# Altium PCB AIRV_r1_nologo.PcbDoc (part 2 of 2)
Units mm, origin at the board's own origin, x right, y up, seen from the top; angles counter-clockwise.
Board outline 65 x 30 mm, 4 copper layers (Top Layer, GND, MidLayer1, Bottom Layer), stack 0.732 mm thick; 130 components, 121 nets, 598 pads, 392 vias.
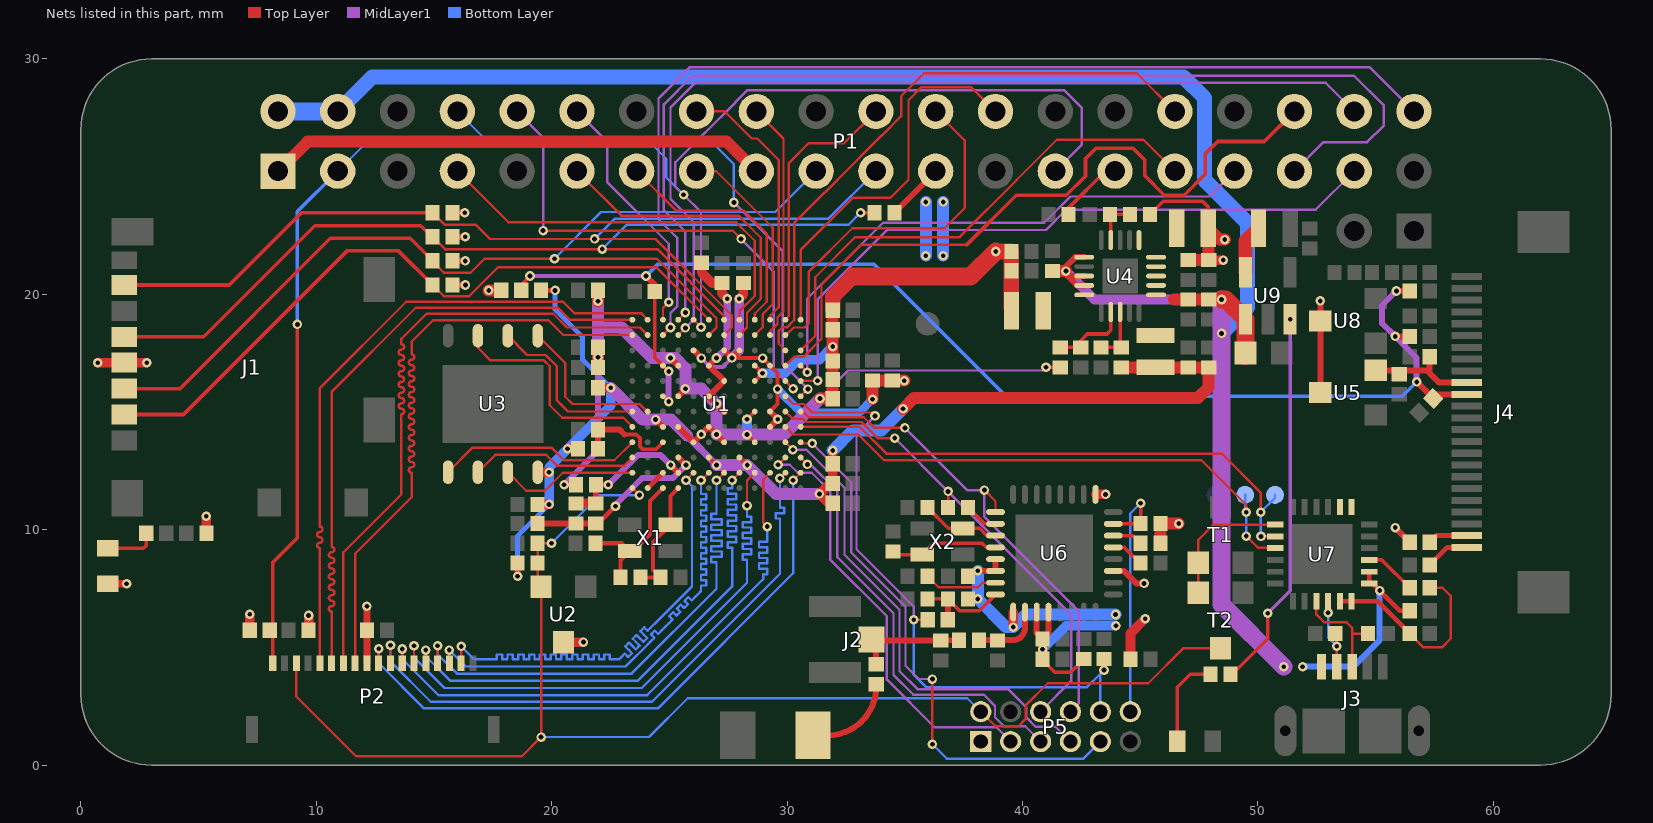
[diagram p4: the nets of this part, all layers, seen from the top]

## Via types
v1: diameter 0.406, hole 0.203, Top Layer to Bottom Layer, tented both sides, 392 vias

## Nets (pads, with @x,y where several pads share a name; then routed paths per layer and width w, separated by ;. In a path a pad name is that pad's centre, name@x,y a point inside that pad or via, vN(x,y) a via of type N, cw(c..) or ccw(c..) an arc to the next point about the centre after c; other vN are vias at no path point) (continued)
I2C_SDA: P1.3 P1.27 P2.1 R17.1 U1.A5 | length 68.6
  Top Layer w0.102: U1.A5@26.024,18.919 v1(26.34,18.604) ; U1.A5@26.027,18.922 U1.A5@26.027,18.952
  Top Layer w0.152: R17.1@8.02,5.731 R17.1@8.15,5.601 ; P2.1@8.15,4.333 R17.1@8.15,5.601 ; v1(9.195,18.72) 9.195,9.652 8.15,8.607 R17.1@8.15,5.601
  MidLayer1 w0.102: v1(26.34,18.604) 26.34,23.495 v1(25.603,24.232) 25.248,24.587 25.248,25.604 26.511,26.868 26.524,26.868 27.788,28.131 27.788,28.144 28.316,28.672 28.329,28.672 28.333,28.677 41.76,28.677 42.52,27.917 42.52,26.36 P1.27@41.39,25.23
  Bottom Layer w0.102: P1.3@10.91,25.23 11.969,26.289 24.333,26.289 24.867,25.756 24.867,24.968 v1(25.603,24.232)
  Bottom Layer w0.152: v1(9.195,18.72) 9.195,23.515 P1.3@10.91,25.23
I2S_BCK: P1.12 U1.A3 | length 10.6
  Top Layer w0.102: U1.A3@24.724,18.919 24.724,19.416 v1(24.968,19.66)
  MidLayer1 w0.102: P1.12@21.07,27.77 22.352,26.488 22.352,24.765 24.968,22.149 v1(24.968,19.66)
I2S_DI: P1.38 U1.B4 | length 40.3
  Top Layer w0.102: U1.B4@25.377,18.272 v1(25.679,18.575)
  MidLayer1 w0.102: v1(25.679,18.575) 26.035,18.93 26.035,23.063 25.044,24.054 25.044,27.941 26.085,28.981 52.879,28.981 P1.38@54.09,27.77
I2S_DO: P1.40 U1.B3 | length 44
  Top Layer w0.102: U1.B3@24.727,18.272 v1(25.044,18.59)
  MidLayer1 w0.102: v1(25.044,18.59) 25.044,19.202 25.324,19.482 25.324,22.403 24.536,23.19 24.536,28.321 25.857,29.642 54.758,29.642 P1.40@56.63,27.77
I2S_WS: P1.35 U1.A4 | length 46.7
  Top Layer w0.102: U1.A4@25.374,18.919 v1@25.679,19.225
  MidLayer1 w0.102: v1(25.679,19.228) 25.679,22.657 24.765,23.571 24.765,28.067 25.984,29.286 54.077,29.286 55.347,28.016 55.347,27.178 54.635,26.467 52.787,26.467 P1.35@51.55,25.23
IO11: P1.37 U1.E12 | length 29.2
  Top Layer w0.102: U1.E12@30.574,16.319 30.574,16.332 v1(31.293,16.332)
  MidLayer1 w0.102: v1(31.293,16.332) 31.293,19.787 34.239,22.733 40.996,22.733 41.859,23.597 52.457,23.597 P1.37@54.09,25.23
IO_12: P1.36 U1.D11 | length 30.4
  Top Layer w0.102: U1.D11@29.924,16.969 30.297,17.342 30.689,17.342 31.461,18.114 31.461,20.422 33.138,22.098 37.617,22.098
  Top Layer w0.152: 37.617,22.098 39.726,24.206 41.859,24.206 42.672,25.019 42.672,25.756 43.129,26.213 44.679,26.213 45.187,25.705 45.187,25.044 46.017,24.214 46.871,24.214 47.752,25.095 47.752,25.959 48.285,26.492 50.272,26.492 P1.36@51.55,27.77
IO_13: P1.33 U1.D12 | length 24
  Top Layer w0.102: U1.D12@30.574,16.969 v1(30.856,16.688) v1@30.856,16.716
  MidLayer1 w0.102: v1(30.856,16.688) 30.856,19.816 34.077,23.038 40.609,23.038 40.919,23.038 42.037,24.155 47.935,24.155 P1.33@49.01,25.23
IO_14: P1.32 U1.C11 | length 25.9
  Top Layer w0.102: U1.C11@29.924,17.619 29.642,17.902 29.642,18.448 29.79,18.597 29.994,18.597 30.297,18.9 30.297,23.033 31.591,24.328 31.604,24.328 32.132,24.856 32.132,24.869 34.01,26.746 34.022,26.746 34.849,27.573 34.849,28.423 35.814,29.388 44.852,29.388 P1.32@46.47,27.77
IO_15: P1.31 U1.C12 | length 21.6
  Top Layer w0.102: U1.C12@30.574,17.619 31.191,18.236 31.191,20.726 32.893,22.428 37.324,22.428 39.752,24.856 39.752,24.869 41.452,26.568 45.132,26.568 P1.31@46.47,25.23
IO_17: P1.26 U1.A12 | length 16.5
  Top Layer w0.102: U1.A12@30.574,18.919 30.574,21.887 32.791,24.105 34.392,24.105 35.154,24.867 35.154,28.245 35.712,28.804 37.816,28.804 P1.26@38.85,27.77
IO_18: P1.24 U1.B11 | length 15.7
  Top Layer w0.102: U1.B11@29.924,18.269 29.954,18.269 30.277,18.593 30.734,18.593 30.912,18.771 30.912,20.955 32.766,22.809 36.678,22.809 37.541,23.673 37.541,26.539 P1.24@36.31,27.77
IO_19: P1.22 U1.A11 | length 11.3
  Top Layer w0.102: U1.A11@29.924,18.919 30.074,19.069 30.074,25.578 30.912,26.416 32.416,26.416 P1.22@33.77,27.77
IO_20: P1.18 U1.B10 | length 10.2
  Top Layer w0.102: P1.18@28.69,27.77 29.845,26.615 29.845,19.279 29.591,19.025 29.591,18.745 29.274,18.428 U1.B10@29.274,18.269
IO_21: P1.16 U1.A10 | length 11.3
  Top Layer w0.102: P1.16@26.15,27.77 27.348,27.77 28.499,26.619 28.727,26.619 29.642,25.705 29.642,19.456 29.274,19.089 U1.A10@29.274,18.919
IO_22: P1.15 U1.B9 | length 9.1
  Top Layer w0.102: P1.15@26.15,25.23 26.987,25.23 29.388,22.829 29.388,19.583 28.956,19.152 28.956,18.601 U1.B9@28.624,18.269
IO_23: P1.13 U1.A9 | length 10.5
  Top Layer w0.102: P1.13@23.61,25.23 25.294,23.546 28.169,23.546 29.134,22.581 29.134,19.685 28.624,19.175 U1.A9@28.624,18.919
IO_24: P1.11 U1.B8 | length 13.5
  Top Layer w0.102: P1.11@21.07,25.23 22.957,23.343 27.94,23.343 28.88,22.403 28.88,19.804 28.296,19.22 28.296,18.591 U1.B8@27.974,18.269
IO_25: P1.7 U1.A8 | length 17.5
  Top Layer w0.102: P1.7@15.99,25.23 18.157,23.063 27.833,23.063 28.621,22.276 28.621,19.934 27.974,19.287 U1.A8@27.974,18.919
ISP_RX: TP3.1 U1.H11 U7.21 | length 24.5
  Top Layer w0.102: U1.H11@29.927,14.372 30.253,14.046 33.02,14.046 34.112,12.954 47.6,12.954 49.505,11.049 v1(49.505,10.744) ; v1(49.505,9.728) 50.001,9.231 50.73,9.231 U7.21@50.73,9.216
  Bottom Layer w0.102: TP3.1@49.454,11.481 49.454,10.795 v1(49.505,10.744) v1(49.505,9.728)
ISP_TX: TP5.1 U1.H12 U7.20 | length 24.1
  Top Layer w0.102: U1.H12@30.577,14.372 33.075,14.372 34.214,13.233 48.463,13.233 50.114,11.582 v1(50.114,10.744) ; v1(50.128,9.716) U7.20@50.73,9.716
  Bottom Layer w0.102: v1@50.114,9.73 v1(50.114,10.744) 50.724,11.354 TP5.1@50.724,11.481
LCD_CS: P2.5 U1.A2 | length 28
  Top Layer w0.102: P2.5@10.15,4.333 10.15,9.144 10.15,9.22 cw(c10.15,9.335) 10.15,9.449 ccw(c10.15,9.563) 10.15,9.677 cw(c10.15,9.792) 10.15,9.906 ccw(c10.15,10.02) 10.15,10.135 10.15,16.017 13.818,19.685 20.472,19.685 20.955,19.202 23.791,19.202 U1.A2@24.074,18.919
LCD_DC: P2.7 U1.B2 | length 27.8
  Top Layer w0.102: P2.7@11.15,4.333 11.15,9.042 13.614,11.506 13.614,14.808 13.614,14.91 ccw(c13.614,15.024) 13.614,15.138 cw(c13.617,15.253) 13.614,15.367 ccw(c13.614,15.481) 13.614,15.596 cw(c13.614,15.71) 13.614,15.824 ccw(c13.614,15.938) 13.614,16.053 cw(c13.614,16.167) 13.614,16.281 ccw(c13.614,16.396) 13.614,16.51 cw(c13.614,16.624) 13.614,16.739 ccw(c13.614,16.853) 13.614,16.967 cw(c13.614,17.081) 13.614,17.196 ccw(c13.614,17.31) 13.614,17.424 cw(c13.614,17.539) 13.614,17.653 ccw(c13.614,17.767) 13.614,17.882 13.614,18.11 14.681,19.177 20.066,19.177 20.65,18.593 23.751,18.593 U1.B2@24.074,18.269 ; U1.B2@24.077,18.272 U1.B2@24.091,18.272
LCD_RST: P2.6 U1.A1 | length 27.6
  Top Layer w0.102: P2.6@10.65,4.333 10.65,6.426 10.65,6.528 cw(c10.65,6.642) 10.65,6.756 ccw(c10.65,6.871) 10.65,6.985 cw(c10.65,7.099) 10.65,7.214 ccw(c10.65,7.328) 10.65,7.442 cw(c10.65,7.556) 10.65,7.671 ccw(c10.65,7.785) 10.65,7.899 cw(c10.65,8.014) 10.65,8.128 ccw(c10.65,8.242) 10.65,8.357 cw(c10.65,8.471) 10.65,8.585 ccw(c10.65,8.7) 10.65,8.814 cw(c10.65,8.928) 10.65,9.042 ccw(c10.65,9.157) 10.65,9.271 10.65,12.268 10.65,15.672 10.65,15.857 14.224,19.431 20.269,19.431 20.777,18.923 U1.A1@23.426,18.923
LCD_WR: P2.8 U1.B1 | length 27.5
  Top Layer w0.102: P2.8@11.65,4.333 11.65,8.983 14.046,11.379 14.046,12.268 14.046,12.421 cw(c14.046,12.535) 14.046,12.649 ccw(c14.046,12.763) 14.046,12.878 cw(c14.046,12.992) 14.046,13.106 ccw(c14.046,13.221) 14.046,13.335 cw(c14.046,13.449) 14.046,13.564 ccw(c14.046,13.678) 14.046,13.792 cw(c14.046,13.906) 14.046,14.021 ccw(c14.046,14.135) 14.046,14.249 cw(c14.046,14.364) 14.046,14.478 ccw(c14.046,14.592) 14.046,14.707 cw(c14.046,14.821) 14.046,14.935 ccw(c14.046,15.05) 14.046,15.164 cw(c14.046,15.278) 14.046,15.392 ccw(c14.046,15.507) 14.046,15.621 cw(c14.046,15.735) 14.046,15.85 ccw(c14.046,15.964) 14.046,16.078 cw(c14.046,16.192) 14.046,16.307 ccw(c14.046,16.421) 14.046,16.535 cw(c14.046,16.65) 14.046,16.764 ccw(c14.046,16.878) 14.046,16.993 cw(c14.046,17.107) 14.046,17.221 ccw(c14.046,17.335) 14.046,17.45 14.046,17.983 14.961,18.898 19.863,18.898 20.488,18.272 U1.B1@23.427,18.272
NetA1_1: A1.1 R42.1 | length 4
  Top Layer w0.254: A1.1@31.1,1.285 A1.1@31.1,1.27 31.724,1.27 ccw(c31.724,3.328) 33.782,3.328 R42.1@33.782,3.436
NetC5_2: C5.2 R1.2 U1.J3 | length 4.3
  Top Layer w0.152: 23.089,14.046 23.597,14.046 23.749,13.894 23.749,13.538 23.876,13.411 24.416,13.411 U1.J3@24.724,13.719 U1.J3@24.727,13.722
  Top Layer w0.254: R1.2@21.964,13.437 C5.2@21.964,14.249 22.885,14.249 23.089,14.046
NetC6_1: C6.1 C7.1 R4.2 U1.K4 | length 7.8
  Top Layer w0.203: C7.1@21.869,10.268 21.978,10.268 v1(22.708,10.998)
  Top Layer w0.254: R4.2@19.399,10.262 19.406,10.268 C6.1@21.031,10.268 C7.1@21.869,10.268 ; U1.K4@25.377,13.072 v1(25.702,12.747)
  MidLayer1 w0.254: v1(22.708,10.998) 22.708,11.065 23.835,12.192 25.148,12.192 v1(25.702,12.747)
NetC6_2: C6.2 C7.2 R2.1 U1.L4 | length 6
  Top Layer w0.254: C7.2@21.869,11.118 21.888,11.137 R2.1@21.888,11.913 v1(22.403,11.913) ; v1(25.052,12.747) U1.L4@25.377,12.422
  Top Layer w0.406: C6.2@21.031,11.118 C7.2@21.869,11.118
  MidLayer1 w0.254: v1(22.403,11.913) 23.675,13.184 24.615,13.184 v1(25.052,12.747)
NetC8_2: C8.2 R5.1 U1.M3 X1.1 | length 6.2
  Top Layer w0.178: C8.2@21.863,9.423 22.987,9.423 X1.1@23.317,9.093 ; R5.1@22.918,7.976 22.918,8.694 X1.1@23.317,9.093 ; U1.M3@24.727,11.772 U1.M3@24.724,11.769 24.181,11.226 24.181,9.804 23.47,9.093 X1.1@23.317,9.093
NetC9_1: C9.1 R5.2 U1.M4 X1.3 | length 5.2
  Top Layer w0.178: R5.2@23.768,7.976 C9.1@24.619,7.976 24.308,8.287 24.308,9.474 X1.3@25.044,10.211 25.044,11.44 U1.M4@25.374,11.769 U1.M4@25.377,11.772
NetC35_2: C35.2 R30.2 U7.5 U7.6 | length 8.5
  Top Layer w0.102: C35.2@56.446,5.588 57.03,5.004 57.81,5.004 58.191,5.385 58.191,7.188 57.849,7.531 R30.2@57.296,7.531
  Top Layer w0.203: U7.5@53.48,6.966 U7.6@53.98,6.966 55.086,6.966 56.446,5.607 C35.2@56.446,5.588
NetC41_2: C41.2 J2.1 L4.2 R42.2 | length 4.8
  Top Layer w0.254: J2.1@33.579,5.334 J2.1@33.612,5.302 ; R42.2@33.782,4.286 33.782,5.131 J2.1@33.612,5.302 ; L4.2@37.294,5.309 C41.2@36.525,5.302 J2.1@33.612,5.302
NetC50_2: C50.2 U6.28 X2.1 | length 4.7
  Top Layer w0.152: C50.2@34.493,9.075 34.627,8.941 X2.1@35.738,8.941 36.216,9.419 38.283,9.419 38.451,9.25 U6.28@38.851,9.25
NetC51_1: C51.1 U6.27 X2.3 | length 3.4
  Top Layer w0.152: C51.1@35.96,10.947 36.849,10.058 X2.3@37.465,10.058 38.176,10.058 38.485,9.75 U6.27@38.851,9.75
NetD1_2: D1.2 J3.3 U7.3 | length 4.6
  Top Layer w0.102: U7.3@52.48,6.966 52.48,6.397 52.807,6.071 53.772,6.071 53.772,6.065 54,5.837 J3.3@54,4.18 ; 54,5.588 D1.2@54.668,5.588
NetD2_2: D2.2 J3.2 U7.4 | length 3.5
  Top Layer w0.102: v1(52.98,6.473) U7.4@52.98,6.966 ; D2.2@53.282,5.588 53.35,5.52 v1(53.35,5.055) J3.2@53.35,4.18
  Bottom Layer w0.102: v1(52.98,6.473) 52.98,5.425 v1(53.35,5.055)
NetDS1_K: DS1.K R49.2 | length 2.2
  Top Layer w0.152: DS1.K@1.143,9.208 2.655,9.208 2.775,9.329 R49.2@2.775,9.855
NetDS3_A: DS3.A R43.2 | length 3.9
  Top Layer w0.152: DS3.A@46.57,1.016 46.57,3.314 47.117,3.861 R43.2@47.987,3.861
NetJ4_23: J4.23 R38.1 | length 1.7
  Top Layer w0.203: R38.1@57.296,9.474 57.571,9.75 J4.23@58.875,9.75
NetJ4_24: J4.24 R33.1 | length 1.9
  Top Layer w0.203: R33.1@57.296,8.503 58.043,9.25 J4.24@58.875,9.25
NetL1_1: L1.1 U4.11
NetL2_1: L2.1 U4.20
NetL3_1: L3.1 U4.6
NetL5_2: L5.2 U9.5 | length 2.1
  Top Layer w0.61: U9.5@49.469,20.939 49.469,22.255 L5.2@50.023,22.809
NetP1_23: P1.23 R23.2 | length 2.5
  Top Layer w0.254: R23.2@34.563,23.47 36.31,25.217 P1.23@36.31,25.23
NetP1_29: P1.29 R21.1 | length 2.9
  Top Layer w0.152: R21.1@41.954,23.393 41.954,23.666 43.518,25.23 P1.29@43.93,25.23
NetR8_2: R8.2 R9.1 U4.3 | length 2.4
  Top Layer w0.152: R9.1@43.332,17.748 R8.2@44.196,17.748 44.145,17.799 U4.3@44.145,19.252
NetR10_2: R10.2 R11.1 U4.14 | length 2
  Top Layer w0.152: U4.14@43.745,22.302 43.745,23.355 R11.1@43.707,23.393 R10.2@44.558,23.393
NetR12_2: R12.2 R13.1 U4.2 | length 3.4
  Top Layer w0.152: R12.2@41.605,17.748 R13.1@42.469,17.748 42.469,18.034 42.748,18.313 43.586,18.313 43.745,18.472 U4.2@43.745,19.252
NetR15_1: R15.1 U6.31 | length 3.2
  Top Layer w0.102: R15.1@35.96,8.026 36.437,7.549 38.1,7.549 38.301,7.75 U6.31@38.851,7.75
NetR16_2: R16.2 U6.26 | length 1.5
  Top Layer w0.152: R16.2@37.687,10.947 38.384,10.25 U6.26@38.851,10.25
NetR19_2: R19.2 U6.13 | length 1.4
  Top Layer w0.152: U6.13@43.851,9.25 44.313,9.25 44.952,8.611 R19.2@45.016,8.611
NetR26_2: R26.2 U6.14 | length 1.3
  Top Layer w0.152: U6.14@43.851,9.75 44.689,9.75 R26.2@45.016,9.423
NetR30_1: R30.1 U7.9 | length 2.2
  Top Layer w0.152: U7.9@54.73,8.716 55.26,8.716 R30.1@56.446,7.531
NetR43_1: R43.1 U9.3 | length 16.2
  Top Layer w0.152: R43.1@48.837,3.861 48.837,3.981 48.871,4.014 49.062,4.014 50.419,5.371 v1(50.419,6.452)
  MidLayer1 w0.152: v1(50.419,6.452) 51.369,7.402 v1(51.369,18.939)
NetU1_G1: U1.G1 U3.2 | length 7.5
  Top Layer w0.102: U3.2@18.136,18.244 18.956,17.424 19.736,17.424 20.218,16.942 20.218,15.494 20.69,15.022 U1.G1@23.427,15.022
NetU1_G2: U1.G2 U3.1 | length 6.8
  Top Layer w0.102: U3.1@19.406,18.244 20.574,17.076 20.574,15.646 20.879,15.342 23.722,15.342 24.042,15.022 U1.G2@24.077,15.022
NetU1_H1: U1.H1 U3.3 | length 9.4
  Top Layer w0.102: U3.3@16.866,18.244 16.866,17.729 17.399,17.196 19.664,17.196 19.914,16.947 19.914,15.291 20.447,14.757 23.042,14.757 U1.H1@23.427,14.372
NetU1_J1: U1.J1 U3.5 | length 8.8
  Top Layer w0.102: U3.5@15.596,12.444 16.639,13.487 19.99,13.487 20.523,12.954 22.659,12.954 U1.J1@23.424,13.719 ; U1.J1@23.424,13.722 U1.J1@23.427,13.722
NetU1_K1: U1.K1 U3.6 | length 7.2
  Top Layer w0.102: U3.6@16.866,12.444 17.605,13.183 19.761,13.183 20.218,12.725 23.08,12.725 U1.K1@23.424,13.069 ; U1.K1@23.424,13.072 U1.K1@23.427,13.072
NetU1_L1: U1.L1 U3.7 | length 5.9
  Top Layer w0.102: U3.7@18.136,12.444 18.921,11.659 19.71,11.659 20.471,12.419 U1.L1@23.424,12.419 ; U1.L1@23.424,12.422 U1.L1@23.427,12.422
NetU1_L3: U1.L3 U1.M2 | length 0.9
  Top Layer w0.203: U1.M2@24.077,11.772 U1.L3@24.727,12.422
NR: C52.1 R7.2 R35.1 U6.32 | length 4.3
  Top Layer w0.152: C52.1@35.96,7.061 R7.2@36.837,7.061 36.837,7.035 37.318,6.553 38.154,6.553 U6.32@38.851,7.25
  Top Layer w0.254: R35.1@36.823,6.172 R7.2@36.823,7.048
RESETN: C46.2 P2.3 P5.2 R3.1 T2.3 U1.M1 U2.2 | length 58.9
  Top Layer w0.102: P2.3@9.15,4.333 9.15,2.915 11.684,0.381 18.735,0.381 v1(19.548,1.194) U2.2@19.548,7.576 19.399,7.725 R3.1@19.399,8.585 C46.2@19.399,9.423 v1(19.99,9.423) ; U1.M1@23.424,11.769 v1(23.724,11.47) ; P5.2@38.225,2.27 38.844,1.651 39.827,1.651 40.132,1.956 40.132,2.54 41.072,3.48 45.339,3.48 46.831,4.972 T2.3@48.412,4.972
  Bottom Layer w0.102: v1(19.548,1.194) 24.13,1.194 25.781,2.845 37.65,2.845 P5.2@38.225,2.27 ; v1(19.99,9.423) 22.036,11.47 v1(23.724,11.47)
RF: C42.2 L4.1 U6.2 | length 2.9
  Top Layer w0.254: L4.1@38.144,5.309 39.573,5.309 ccw(c39.573,5.837) 40.101,5.837 U6.2@40.101,6.5
RTS: T1.1 T2.2 U7.19 | length 5.8
  Top Layer w0.102: T2.2@47.462,7.322 47.462,9.566 48.113,10.216 U7.19@50.73,10.216
RX1: P1.10 U1.E11 | length 21.8
  Top Layer w0.102: v1(19.634,22.708) 27.686,22.708 v1(28.042,22.352) ; U1.E11@29.924,16.319 v1(30.251,15.992)
  MidLayer1 w0.102: P1.10@18.53,27.77 19.634,26.666 v1(19.634,22.708) ; v1(28.042,22.352) 29.439,20.955 29.439,16.805 v1(30.251,15.992)
RXT: U7.13
SPI0_D0: P2.10 U1.L12 | length 26.4
  Top Layer w0.102: P2.10@12.65,4.333 v1(12.65,4.943) ; v1@30.251,12.097 U1.L12@30.577,12.422
  Bottom Layer w0.102: v1(12.65,4.943) 12.65,4.343 14.58,2.413 24.511,2.413 30.251,8.153 v1@30.251,12.097
  other v1: 30.251,12.1
SPI0_D1: P2.11 U1.L11 | length 26
  Top Layer w0.102: P2.11@13.15,4.333 v1(13.15,5.089) ; v1@29.697,12.167 U1.L11@29.927,12.422
  Bottom Layer w0.102: v1(13.15,5.089) 13.15,4.401 14.859,2.692 24.257,2.692 29.697,8.132 29.697,10.389 29.697,10.477 29.519,10.477 29.519,10.706 29.697,10.706 29.875,10.706 29.875,10.935 29.697,10.935 29.697,11.049 v1@29.697,12.167
  other v1: 29.693,12.188
SPI0_D2: P2.12 U1.L10 | length 26.1
  Top Layer w0.102: P2.12@13.65,4.333 v1(13.65,4.933) ; v1(29.159,10.135) 28.981,10.312 28.981,12.127 U1.L10@29.274,12.419 U1.L10@29.277,12.422
  Bottom Layer w0.102: v1(13.65,4.933) 13.65,4.511 15.189,2.972 24.054,2.972 28.981,7.899 28.981,8.026 28.981,8.115 29.159,8.115 29.159,8.344 28.981,8.344 28.804,8.344 28.804,8.572 28.981,8.572 29.159,8.572 29.159,8.801 28.981,8.801 28.804,8.801 28.804,9.03 28.981,9.03 29.159,9.03 29.159,9.258 28.981,9.258 28.804,9.258 28.804,9.487 28.981,9.487 29.159,9.487 29.159,9.716 v1(29.159,10.135)
SPI0_D3: P2.13 U1.L9 | length 25.4
  Top Layer w0.102: P2.13@14.15,4.333 v1(14.15,5.068) ; v1(28.296,11.024) 28.296,12.091 U1.L9@28.624,12.419 U1.L9@28.627,12.422
  Bottom Layer w0.102: v1(14.15,5.068) 14.15,4.57 15.443,3.277 23.825,3.277 28.296,7.747 28.296,8.712 28.296,8.725 28.118,8.725 28.118,8.954 28.296,8.954 28.473,8.954 28.473,9.182 28.296,9.182 28.118,9.182 28.118,9.411 28.296,9.411 28.473,9.411 28.473,9.639 28.296,9.639 28.118,9.639 28.118,9.868 28.296,9.868 28.473,9.868 28.473,10.096 28.296,10.096 28.118,10.096 28.118,10.325 28.296,10.325 28.473,10.325 28.473,10.554 28.296,10.554 28.296,10.668 v1(28.296,11.024)
SPI0_D4: P2.14 U1.L8 | length 24.8
  Top Layer w0.102: P2.14@14.65,4.333 v1(14.65,4.887) ; v1@27.661,12.106 U1.L8@27.974,12.419 U1.L8@27.977,12.422
  Bottom Layer w0.102: v1(14.65,4.887) 14.65,4.629 15.697,3.581 23.647,3.581 27.661,7.595 27.661,9.169 27.661,9.242 27.483,9.242 27.483,9.471 27.661,9.471 27.838,9.471 27.838,9.7 27.661,9.7 27.483,9.7 27.483,9.928 27.661,9.928 27.838,9.928 27.838,10.157 27.661,10.157 27.483,10.157 27.483,10.385 27.661,10.385 27.838,10.385 27.838,10.614 27.661,10.614 27.483,10.614 27.483,10.843 27.661,10.843 27.838,10.843 27.838,11.071 27.661,11.071 27.483,11.071 27.483,11.3 27.661,11.3 27.838,11.3 27.838,11.528 27.661,11.528 27.483,11.528 27.483,11.757 27.661,11.757 27.661,11.986 v1(27.661,12.1)
SPI0_D5: P2.15 U1.L7 | length 24
  Top Layer w0.102: P2.15@15.15,4.333 v1(15.15,5.071) ; v1@26.975,12.07 U1.L7@27.327,12.422
  Bottom Layer w0.102: v1(15.15,5.071) 15.15,4.713 15.977,3.886 23.393,3.886 27,7.493 27,8.433 27,8.619 26.772,8.619 26.772,8.848 27,8.848 27.229,8.848 27.229,9.077 27,9.077 26.772,9.077 26.772,9.305 27,9.305 27.229,9.305 27.229,9.534 27,9.534 26.772,9.534 26.772,9.762 27,9.762 27.229,9.762 27.229,9.991 27,9.991 26.772,9.991 26.772,10.22 27,10.22 27.229,10.22 27.229,10.448 27,10.448 26.772,10.448 26.772,10.677 27,10.677 27,10.905 27,11.02 27,11.655 v1@27,12.09
  other v1: 27,12.1
SPI0_D6: P2.16 U1.L6 | length 23.8
  Top Layer w0.102: P2.16@15.65,4.333 v1(15.65,4.889) ; v1@26.34,12.085 U1.L6@26.677,12.422
  Bottom Layer w0.102: v1(15.65,4.889) 16.348,4.191 23.139,4.191 24.105,5.156 24.199,5.251 24.361,5.412 24.217,5.556 24.379,5.718 24.523,5.574 24.684,5.736 24.765,5.817 24.813,5.865 24.975,6.027 25.137,6.188 24.993,6.332 25.155,6.494 25.298,6.35 25.46,6.512 25.316,6.655 25.478,6.817 25.622,6.673 25.783,6.835 25.64,6.979 25.801,7.14 25.945,6.997 26.107,7.158 26.187,7.239 26.34,7.391 26.34,7.404 26.34,7.633 26.568,7.633 26.568,7.861 26.34,7.861 26.34,8.09 26.568,8.09 26.568,8.319 26.34,8.319 26.34,8.547 26.568,8.547 26.568,8.776 26.34,8.776 26.34,9.004 26.568,9.004 26.568,9.233 26.34,9.233 26.34,9.461 26.568,9.461 26.568,9.69 26.34,9.69 26.34,9.919 26.568,9.919 26.568,10.147 26.34,10.147 26.34,10.376 26.568,10.376 26.568,10.604 26.34,10.604 26.34,10.833 26.568,10.833 26.568,11.062 26.34,11.062 26.34,11.29 26.568,11.29 26.568,11.519 26.34,11.519 26.34,11.633 v1@26.34,12.085
  other v1: 26.34,12.1
SPI0_D7: P2.17 U1.L5 | length 24
  Top Layer w0.102: P2.17@16.15,4.333 16.154,4.338 v1(16.154,5.045) ; v1(25.705,12.1) U1.L5@26.027,12.422
  Bottom Layer w0.102: v1(16.154,5.045) 16.704,4.496 17.094,4.496 17.209,4.496 17.437,4.496 17.666,4.496 17.666,4.699 17.894,4.699 17.894,4.496 18.123,4.496 18.123,4.699 18.351,4.699 18.351,4.496 18.58,4.496 18.58,4.699 18.809,4.699 18.809,4.496 19.037,4.496 19.037,4.699 19.266,4.699 19.266,4.496 19.494,4.496 19.494,4.699 19.723,4.699 19.723,4.496 19.952,4.496 19.952,4.699 20.18,4.699 20.18,4.496 20.409,4.496 20.409,4.699 20.637,4.699 20.637,4.496 20.866,4.496 20.866,4.699 21.095,4.699 21.095,4.496 21.323,4.496 21.323,4.699 21.552,4.699 21.552,4.496 21.78,4.496 21.78,4.699 22.009,4.699 22.009,4.496 22.238,4.496 22.238,4.699 22.466,4.699 22.466,4.496 22.695,4.496 22.86,4.496 22.941,4.577 23.102,4.738 23.246,4.595 23.408,4.756 23.264,4.9 23.12,5.044 23.282,5.205 23.426,5.062 23.569,4.918 23.731,5.08 23.587,5.223 23.444,5.367 23.605,5.529 23.749,5.385 23.893,5.241 24.054,5.403 23.911,5.546 23.767,5.69 23.929,5.852 24.072,5.708 24.181,5.817 24.486,6.121 25.959,7.595 25.959,11.846 v1(25.705,12.1)
TCK: P5.3 U1.K11 | length 18.5
  Top Layer w0.102: v1(29.616,12.762) U1.K11@29.924,13.069
  MidLayer1 w0.102: v1(29.616,12.762) 30.114,12.762 30.456,12.419 31.045,12.419 31.826,11.638 31.826,8.738 34.239,6.325 34.239,3.632 36.264,1.608 38.887,1.608 P5.3@39.495,1
TDI: P5.5 U1.K12 | length 18.6
  Top Layer w0.102: U1.K12@30.574,13.069 30.574,13.063 v1(30.861,12.776)
  MidLayer1 w0.102: v1(30.861,12.776) 30.988,12.776 32.131,11.633 32.131,8.839 34.519,6.452 34.519,3.835 35.357,2.997 38.35,2.997 38.827,2.52 38.827,2.032 39.208,1.651 40.114,1.651 P5.5@40.765,1
TDO: P5.9 U1.J12 | length 23.4
  Top Layer w0.102: U1.J12@30.574,13.719 30.628,13.665 v1(31.064,13.665) ; v1(36.17,0.889) v1(36.17,3.658)
  MidLayer1 w0.102: v1(31.064,13.665) 32.715,12.014 32.715,9.042 35.027,6.731 35.027,4.222 35.591,3.658 v1(36.17,3.658)
  Bottom Layer w0.102: v1(36.17,0.889) 36.779,0.279 42.584,0.279 P5.9@43.305,1
TF_CLK: J1.5 R20.2 R23.1 U1.A7 | length 41.4
  Top Layer w0.102: R20.2@14.942,22.445 15.489,21.898 15.511,21.92 v1(22.149,21.92) 24.486,21.92 27.324,19.082 U1.A7@27.324,18.919
  Top Layer w0.152: J1.5@1.839,18.195 5.216,18.195 9.931,22.911 14.434,22.911 R20.2@14.942,22.403 ; v1(33.122,23.47) R23.1@33.713,23.47
  Bottom Layer w0.102: v1(22.149,21.92) 23.19,22.962 32.614,22.962 v1(33.122,23.47)
TF_CS: J1.2 R28.2 U1.A6 | length 30
  Top Layer w0.102: R28.2@14.942,20.396 15.419,19.919 16.49,19.919 17.729,21.158 24.435,21.158 U1.A6@26.674,18.919
  Top Layer w0.152: J1.2@1.839,14.895 4.354,14.895 11.303,21.844 13.494,21.844 R28.2@14.942,20.396
TF_MISO: J1.7 P1.21 R29.2 U1.B7 | length 43.1
  Top Layer w0.102: R29.2@14.942,23.47 15.45,22.962 16.764,22.962 17.374,22.352 v1(21.819,22.352) 24.409,22.352 27.648,19.114 27.648,18.593 U1.B7@27.327,18.272
  Top Layer w0.152: J1.7@1.839,20.395 6.298,20.395 9.373,23.47 14.815,23.47 R29.2@14.942,23.343
  Bottom Layer w0.102: v1(21.819,22.352) 22.682,23.216 31.756,23.216 P1.21@33.77,25.23
TF_MOSI: J1.3 P1.19 R27.2 U1.B6 | length 43.2
  Top Layer w0.102: R27.2@14.942,21.394 15.418,20.918 16.549,20.918 17.145,21.514 24.472,21.514 27,18.986 27,18.595 U1.B6@26.674,18.269
  Top Layer w0.152: J1.3@1.839,15.995 4.209,15.995 10.592,22.377 13.985,22.377 R27.2@14.942,21.421 R27.2@14.942,21.394
  Bottom Layer w0.102: v1(20.117,21.514) 22.098,23.495 29.495,23.495 P1.19@31.23,25.23
TMS: P5.7 U1.J11 | length 20.8
  Top Layer w0.102: U1.J11@29.924,13.719 v1(30.243,13.4)
  MidLayer1 w0.102: v1(30.243,13.4) 30.821,13.4 32.436,11.786 32.436,8.941 34.773,6.604 34.773,3.988 35.531,3.23 39.387,3.23 40.163,2.454 40.163,2.02 40.557,1.626 41.409,1.626 P5.7@42.035,1
TX1: P1.8 U1.F12 | length 24
  Top Layer w0.102: U1.F12@30.574,15.669 v1(30.881,15.977)
  MidLayer1 w0.102: v1(27.737,23.901) 29.82,21.819 29.82,17.038 v1(30.881,15.977)
  Bottom Layer w0.102: P1.8@15.99,27.77 17.09,26.67 26.594,26.67 27.737,25.527 v1(27.737,23.901)
TXT: U7.14
VCC0V9: C10.2 C11.2 C12.2 C13.2 C14.2 C15.2 C16.2 C17.2 C18.2 C19.2 C32.1 C33.2 L2.2 R2.2 R12.1 U1.D4 U1.D6 U1.D9 U1.E7 U1.E9 U1.F4 U1.F6 U1.G7 U1.G9 U1.H4 U1.H6 U1.J5 U1.J7 U1.J9 | length 67.6
  Top Layer w0.152: v1(28.296,14.691) U1.G9@28.627,15.022 ; v1@28.321,14.028 U1.J9@28.627,13.722 ; v1(40.996,16.898) R12.1@41.605,16.898
  Top Layer w0.178: U1.E9@28.627,16.322 v1(28.952,16.647) U1.D9@28.627,16.972
  Top Layer w0.254: v1(20.523,11.913) R2.2@21.038,11.913 ; v1(25.046,17.297) U1.D4@25.374,16.969 ; U1.H4@25.377,14.372 26.027,13.722 v1(26.352,14.047) 26.677,14.372 v1(27,14.049) U1.J7@27.327,13.722 ; U1.F4@25.377,15.672 v1@25.68,15.975 ; U1.F6@26.677,15.672 27.327,16.322 26.677,16.972 v1(26.999,17.294)
  Top Layer w0.305: U1.F6@26.677,15.672 v1(27,15.349) U1.G7@27.327,15.022
  Top Layer w0.406: C19.2@26.365,21.343 26.365,20.93 26.816,20.479 C17.2@27.229,20.479 27.229,20.041 v1(27.457,19.812)
  Top Layer w0.508: C11.2@21.964,16.891 v1(21.964,17.323) C14.2@21.964,17.755 ; v1(21.964,19.704) C13.2@21.964,20.168 ; v1(31.394,15.57) C12.2@31.935,15.57 C10.2@31.935,16.383 C15.2@31.935,17.17 v1(31.935,17.78) C16.2@31.935,18.491 C18.2@31.935,19.329
  Top Layer w0.66: C18.2@31.944,19.329 31.944,19.904 32.791,20.752 ; v1(38.862,21.819) C32.1@39.529,21.819 C33.2@39.529,21.006 L2.2@39.529,19.439
  Top Layer w0.762: 32.791,20.752 37.795,20.752 v1(38.862,21.819)
  MidLayer1 w0.102: v1(31.394,15.57) 32.588,16.764 40.862,16.764 v1(40.996,16.898)
  MidLayer1 w0.254: v1(20.523,11.913) 21.964,13.354 v1(21.964,17.323)
  MidLayer1 w0.279: v1(26.999,17.294) 27.457,17.753
  MidLayer1 w0.305: 27.457,17.753 v1(27.457,19.812)
  MidLayer1 w0.508: v1(21.964,17.323) 21.964,18.593 ; v1(21.964,19.704) 21.964,18.593 ; v1(27,14.049) v1(27,15.349) 26.356,15.993 v1(25.68,15.993) 25.68,16.865 25.248,17.297 v1(25.046,17.297) 24.257,17.297 22.962,18.593 21.964,18.593 ; v1@27.007,14.042 v1(28.296,14.042) 29.866,14.042 v1(31.394,15.57)
  Bottom Layer w0.406: v1(28.296,14.042) v1(28.296,14.691) ; v1(28.952,16.647) 29.906,16.647 30.48,17.221 31.376,17.221 v1(31.935,17.78)
VCC1V8: C20.2 C21.2 C22.2 C23.2 C24.2 C30.1 C31.2 L3.2 R1.1 R3.2 R8.1 R36.2 U1.H3 U1.K6 U1.K8 U3.8 | length 54.5
  Top Layer w0.178: v1@24.399,14.688 v1(24.409,14.677) v1@24.422,14.677 ; U1.K6@26.677,13.072 v1(27.002,12.747) ; U1.K8@27.977,13.072 v1(28.302,12.747)
  Top Layer w0.203: R36.2@19.544,20.168 v1(20.142,20.168)
  Top Layer w0.254: v1(18.549,8.02) R3.2@18.549,8.585 ; v1@24.422,14.677 U1.H3@24.727,14.372
  Top Layer w0.406: C24.2@19.399,11.074 v1(19.886,11.074) ; U3.8@19.406,12.444 v1(19.886,12.444) ; v1(20.676,13.437) R1.1@21.114,13.437 ; C21.2@21.964,16.027 v1(22.504,16.027) ; C22.2@31.935,11.125 31.765,11.125 v1(31.369,11.521) 31.812,11.963 C23.2@31.935,11.963 C20.2@31.935,12.802 v1(31.935,13.367)
  Top Layer w0.508: v1(34.925,15.138) 35.382,15.596 47.447,15.596 47.904,16.053 C30.1@47.904,16.898 R8.1@44.196,16.898
  MidLayer1 w0.305: 25.754,13.995 v1(27.002,12.747)
  MidLayer1 w0.508: v1(22.504,16.027) 23.855,14.677 v1(24.409,14.677) 25.072,14.677 25.754,13.995 ; v1(27.002,12.747) v1(28.302,12.747) 29.528,11.521 v1(31.369,11.521)
  Bottom Layer w0.203: v1(18.549,8.02) 18.549,9.737 v1(19.886,11.074) ; v1(20.142,20.168) 20.142,19.355 21.311,18.186 21.311,17.221 v1(22.504,16.027)
  Bottom Layer w0.254: v1(27.002,12.747) v1@27.008,12.741 ; v1@28.297,12.741 v1(28.302,12.747)
  Bottom Layer w0.406: v1(19.886,11.074) v1(19.886,12.444) 19.886,12.647 v1(20.676,13.437) 22.504,15.265 v1(22.504,16.027)
  Bottom Layer w0.508: v1(31.935,13.367) 32.791,14.224 34.011,14.224 v1(34.925,15.138)
VCC3V3: C1.1 C2.1 C3.1 C28.1 C29.2 C37.2 C38.2 C39.2 C40.2 C43.1 DS1.A J1.4 L1.2 P1.1 P1.17 P2.9 P5.1 R6.2 R7.1 R10.1 R14.1 R17.2 R18.1 R20.1 R26.1 R27.1 R28.1 R29.1 R32.2 R37.2 R38.2 U1.C5 U1.C7 U1.C8 U1.D10 U1.G10 U1.H10 U2.3 U5.3 U6.1 U6.3 U6.4 U6.11 U6.17 U6.29 U6.30 U8.3 | length 92.4
  Top Layer w0.152: v1(27.652,17.297) v1@27.656,17.293 ; C40.2@40.85,4.496 40.85,4.464 41.364,3.949 42.042,3.949 R32.2@42.596,4.503 ; R10.1@45.408,23.393 45.975,23.96 47.643,23.96 47.894,23.709 L1.2@47.894,22.809
  Top Layer w0.178: v1@27.656,17.293 v1(28.956,17.293) 29.595,16.655 v1(29.595,15.977) 29.595,15.34 U1.G10@29.277,15.022
  Top Layer w0.254: R28.1@15.792,20.396 v1(16.332,20.396) ; R27.1@15.792,21.421 v1(16.324,21.421) ; R20.1@15.792,22.445 v1(16.324,22.445) ; R29.1@15.792,23.47 v1(16.307,23.47) ; U1.C5@26.027,17.622 v1(26.356,17.293) ; U1.C7@27.327,17.622 v1(27.652,17.297) U1.C8@27.974,17.619 U1.C8@27.977,17.622 ; U1.H10@29.277,14.372 v1(29.602,14.697) U1.G10@29.277,15.022 ; R7.1@37.687,7.061 v1(38.1,7.061) ; C38.2@37.687,8.026 37.91,8.25 U6.30@38.851,8.25 U6.29@38.851,8.75 ; U6.3@40.601,6.5 40.601,5.608 C39.2@40.85,5.359 41.101,5.611 U6.4@41.101,6.5 ; U6.11@43.851,8.25 44.305,8.25 44.833,7.722 v1(45.161,7.722) ; U5.3@52.648,15.824 U8.3@52.648,18.872 v1(52.648,19.722) ; v1(55.829,10.091) R38.2@56.446,9.474
  Top Layer w0.305: DS1.A@1.143,7.708 v1(1.942,7.708) ; v1(12.148,6.754) 12.148,6.137 12.15,6.135 P2.9@12.15,4.333
  Top Layer w0.406: v1(0.712,17.095) J1.4@1.839,17.095 v1(2.795,17.095) ; C43.1@5.327,9.855 v1(5.327,10.573) ; R17.2@7.17,5.731 v1(7.17,6.408) ; R6.2@9.671,5.731 v1(9.671,6.357) ; U2.3@20.498,5.226 v1(21.348,5.226) ; v1(27.965,19.812) 28.143,19.99 C2.1@28.143,20.479 ; v1(39.601,5.865) U6.1@39.601,6.5 ; C40.2@40.85,4.496 v1(40.85,4.928) C39.2@40.85,5.359 ; U6.17@43.101,11.5 v1(43.526,11.5) ; R14.1@44.584,4.496 44.584,5.595 v1(45.212,6.223) ; C29.2@47.904,21.456 v1(48.526,21.456)
  Top Layer w0.508: P1.1@8.37,25.23 9.628,26.488 27.432,26.488 P1.17@28.69,25.23 ; v1(17.323,20.168) R37.2@17.856,20.168 ; v1(33.63,15.545) C3.1@33.63,16.339 C1.1@34.468,16.339 34.475,16.332 v1(34.976,16.332) ; R26.1@45.866,9.423 R18.1@45.866,10.262 v1(46.634,10.262) ; C28.1@47.041,21.456 C29.2@47.904,21.456 47.894,21.467 L1.2@47.894,22.809 48.376,22.327 v1(48.59,22.327)
  MidLayer1 w0.152: v1(26.356,17.293) 26.737,16.912 27.267,16.912 v1(27.652,17.297)
  MidLayer1 w0.406: v1(27.652,17.297) 27.965,17.611 v1(27.965,19.812)
  Bottom Layer w0.254: v1@26.32,17.293 v1(26.356,17.293)
  Bottom Layer w0.305: v1@29.597,14.703 v1(29.602,14.697)
  Bottom Layer w0.356: v1(29.595,15.977) 29.595,15.967 30.579,14.982 33.067,14.982 v1(33.63,15.545)
  Bottom Layer w0.406: v1(40.85,4.928) 41.841,5.918 v1(43.967,5.918)
  Bottom Layer w0.508: v1(35.89,21.641) v1(35.89,23.927) ; v1(36.627,21.641) v1(36.627,23.927) ; v1(38.1,8.255) v1(38.1,7.061) 39.296,5.865 v1(39.601,5.865) 40.136,6.4 v1(43.951,6.4)
VCCUSB: C25.1 C26.1 C27.1 C34.2 C53.2 J3.1 P1.2 P1.4 U4.7 U4.8 U4.9 U4.10 U4.16 U4.18 U4.19 U7.7 U7.8 U9.1 | length 92.4
  Top Layer w0.203: U7.8@54.73,8.216 U7.7@54.73,7.716 54.869,7.716 v1(55.169,7.417) 56.026,6.56 C34.2@56.446,6.56
  Top Layer w0.254: v1@41.7,20.987 41.7,21.047 42.23,21.577 U4.16@42.62,21.577 ; v1@41.77,20.917 41.91,20.777 ; U4.19@42.62,20.377 42.31,20.377 41.91,20.777 ; U4.18@42.62,20.777 41.91,20.777
  Top Layer w0.508: C27.1@41.275,20.987 41.7,20.987 v1(41.841,20.987) ; 46.442,19.78 C26.1@47.041,19.78 C25.1@47.904,19.78 v1(48.456,19.78)
  Top Layer w0.762: v1(48.456,19.78) 48.628,19.78 U9.1@49.469,18.939 C53.2@49.469,17.376
  MidLayer1 w0.406: v1(41.841,20.987) 43.048,19.78 v1(48.456,19.78)
  MidLayer1 w0.762: v1(48.456,19.78) v1(48.456,18.339) 48.456,6.818 v1(51.094,4.18)
  Bottom Layer w0.254: v1(51.897,4.18) 54.04,4.18 55.169,5.309 v1(55.169,7.417)
  Bottom Layer w0.635: P1.4@10.91,27.77 12.375,29.235 46.838,29.235 47.727,28.346 47.727,24.86 49.555,23.031 49.555,19.438 v1(48.456,18.339)
  Bottom Layer w0.762: P1.2@8.37,27.77 P1.4@10.91,27.77
VDD1V5: C45.2 C47.1 J4.10 U5.2 | length 4.2
  Top Layer w0.254: 55.524,16.764 57.296,16.764 ; C45.2@57.296,17.348 57.296,16.654 57.7,16.25 J4.10@58.875,16.25
VDDIO67: C4.1 C44.2 J4.11 R36.1 R37.1 R39.2 R40.2 U1.D3 U1.F3 | length 55.7
  Top Layer w0.152: R37.1@18.706,20.168 18.706,20.408 v1(19.075,20.777) ; C4.1@24.377,20.117 C4.1@24.377,20.403 ; C4.1@24.384,20.117 24.384,17.31 U1.D3@24.724,16.969 v1(24.968,16.725) ; U1.F3@24.724,15.669 v1@24.985,15.409
  Top Layer w0.254: v1(24.003,20.777) C4.1@24.377,20.403 ; v1(55.829,18.212) R39.2@56.446,18.212 ; v1(55.88,20.142) R40.2@56.446,20.142 ; v1(56.744,16.281) 57.296,15.729 C44.2@57.296,15.596 ; C44.2@57.296,15.748 57.298,15.75 J4.11@58.875,15.75
  MidLayer1 w0.152: v1(19.075,20.777) v1(24.003,20.777)
  MidLayer1 w0.254: v1(24.968,15.443) v1(24.968,16.725) ; v1(55.88,20.142) 55.27,19.533 55.27,18.771 v1(55.829,18.212) 56.744,17.297 v1(56.744,16.281)
  Bottom Layer w0.152: v1(24.003,20.777) 24.511,21.285 33.68,21.285 39.294,15.672 56.134,15.672 v1(56.744,16.281)
WIFI_BOOT: P5.12 R18.2 U6.15 | length 11.1
  Top Layer w0.152: U6.15@43.851,10.25 45.004,10.25 R18.2@45.016,10.262 v1(45.016,11.125)
  Bottom Layer w0.102: P5.12@44.575,2.27 44.575,10.685 v1(45.016,11.125)
WIFI_EN: P5.10 R34.2 R35.2 U1.F11 | length 27.6
  Top Layer w0.102: U1.F11@29.927,15.672 30.258,15.342 30.705,15.342 31.064,14.982 v1@33.608,14.982 ; v1(35.382,6.172) R35.2@35.973,6.172 ; v1(43.459,4.039) R34.2@43.459,4.503
  MidLayer1 w0.102: v1(33.733,14.834) 32.944,14.044 32.944,9.169 35.382,6.731 v1(35.382,6.172)
  Bottom Layer w0.102: v1(35.382,6.172) 35.382,3.835 35.916,3.302 42.723,3.302 43.305,3.884 ; P5.10@43.305,2.27 43.305,3.884 ; v1(43.459,4.039) 43.305,3.884
WIFI_RXD: P5.8 U1.G12 U6.25 | length 21.5
  Top Layer w0.102: U1.G12@30.574,15.019 30.671,15.019 30.912,14.779 33.253,14.779 33.706,14.326 v1(35.001,14.326) ; v1(38.379,11.684) 38.851,11.212 U6.25@38.851,10.75
  MidLayer1 w0.102: v1(35.001,14.326) 37.643,11.684 v1(38.379,11.684) 38.379,10.541 42.393,6.528 42.393,2.628 P5.8@42.035,2.27
WIFI_TXD: P5.6 R16.1 U1.G11 | length 21.1
  Top Layer w0.102: U1.G11@29.927,15.022 30.243,14.707 30.679,14.707 30.81,14.575 33.159,14.575 33.841,13.894 v1(34.569,13.894) ; R16.1@36.837,10.947 v1(36.837,11.626)
  MidLayer1 w0.102: v1(34.569,13.894) v1(36.837,11.626) 42.062,6.401 42.062,3.567 P5.6@40.765,2.27
pads on no net: A1.2 J1.1 J1.8 J3.4 J4.1 M2.0 U6.5 U6.6 U6.8 U6.9 U6.10 U6.12 U6.16 U6.18 U6.19 U6.20 U6.21 U6.22 U6.23 U6.24 U7.1 U7.10 U7.11 U7.12 U7.15 U7.16 U7.17 U7.18 U7.22 U7.24

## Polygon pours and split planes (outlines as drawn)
VCC3V3 on MidLayer1 "t" (solid, remove dead copper, pour order 0): -0.924,30.472 -0.315,31.082 65.446,31.082 65.446,0.577 64.151,-0.719 -0.365,-0.719
GND on Top Layer "top" (solid, remove dead copper, pour order 2): -0.406,31.09 65.278,31.09 65.329,31.039 65.608,30.759 65.608,-0.33 -0.813,-0.33 -0.991,-0.152
GND on Bottom Layer "t" (solid, remove dead copper, pour order 4): -0.864,30.836 -0.432,31.267 65.71,31.267 65.71,-0.813 65.507,-1.016 65.1,-0.61 -1.067,-0.61
GND on GND (split plane): 62.217,29.482 62.433,29.454 62.645,29.407 62.852,29.342 63.053,29.258 63.246,29.158 63.429,29.041 63.602,28.909 63.762,28.762 63.909,28.602 64.041,28.429 64.158,28.246 64.258,28.053 64.342,27.852 64.407,27.645 64.454,27.433 64.482,27.217 64.491,27.016 64.49,27 64.49,3 64.491,2.984 64.482,2.783 64.454,2.567 64.407,2.355 64.342,2.148 64.258,1.947 64.158,1.754 64.041,1.571 63.909,1.398 63.762,1.238 63.602,1.091 63.429,0.959 63.246,0.842 63.053,0.742 62.852,0.658 62.645,0.593 62.433,0.546 62.217,0.518 62.016,0.509 62,0.51 33.096,0.51 33.096,2.819 25.781,2.819 25.781,0.51 3,0.51 2.984,0.509 2.783,0.518 2.567,0.546 2.355,0.593 2.148,0.658 1.947,0.742 1.754,0.842 1.571,0.959 1.398,1.091 1.238,1.238 1.091,1.398 0.959,1.571 0.842,1.754 0.742,1.947 0.658,2.148 0.593,2.355 0.546,2.567 0.518,2.783 0.509,2.984 0.51,3 0.51,27 0.509,27.016 0.518,27.217 0.546,27.433 0.593,27.645 0.658,27.852 0.742,28.053 0.842,28.246 0.959,28.429 1.091,28.602 1.238,28.762 1.398,28.909 1.571,29.041 1.754,29.158 1.947,29.258 2.148,29.342 2.355,29.407 2.567,29.454 2.783,29.482 2.984,29.491 3,29.49 62,29.49 62.016,29.491

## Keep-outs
Keep-Out Layer:
  circle w0.127: c61.5,26.5 r1.375
  circle w0.127: c61.5,3.5 r1.375
  circle w0.127: c3.5,3.5 r1.375
  circle w0.127: c3.5,26.5 r1.375
  lines w0.127: 0,3 ccw(c3,3) 3,0 17.75,0 47.25,0 62,0 ccw(c62,3) 65,3 65,27 ccw(c62,27) 62,30 3,30 ccw(c3,27) 0,27 0,3

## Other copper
Top Layer:
  rectangle net VCCUSB: 50.749,3.886 52.883,4.724
  rectangle net NetL2_1: 41.123,18.974 43.002,20.091
  rectangle net NetL1_1: 44.856,22.2 46.838,22.657
  rectangle net VCCUSB: 46.203,19.533 46.609,21.057
  rectangle net VCCUSB: 45.745,20.193 46.609,21.768
  rectangle net NetL3_1: 45.314,18.009 45.847,20.041
  pour cut-out: 25.781,0.051 25.781,2.819 33.096,2.819 33.096,0.051
MidLayer1:
  rectangle net VCCUSB: 50.749,3.886 52.375,4.724
  pour cut-out: 25.781,0.051 25.781,2.819 33.109,2.819 33.109,0.051
Bottom Layer:
  pour cut-out: 25.781,0.051 25.781,2.819 33.109,2.819 33.109,0.051
GND (plane layer: these items are gaps in the copper):
  rectangle: 25.781,0.015 33.096,2.819

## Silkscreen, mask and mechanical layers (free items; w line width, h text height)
Top Overlay:
  lines w0.127: 28.854,22.962 32.309,22.962 32.309,21.717 28.854,21.717 28.854,23.96
  text "BAT" at 58.039,22.708 h1.4
  text "GPIO" at 28.931,21.844 h1.52
  text "-" at 54.839,21.463 h1.52
  text "-" at 55.118,21.463 h1.52
  text "+" at 55.956,21.336 h1.52
  text "TF CARD" at 13.132,18.872 h1.4
  text "H2.0" at 62.611,13.792 h1.4 r90
  text "DVP" at 58.029,11.515 h1.4 r90
  text "PWR" at 1.829,8.026 h1.4
  text "AIRV" at 8.509,7.772 h3.81
  text "LCD" at 12.446,6.274 h1.4
  text "What will you make?" at 17.958,3.658 h1.52
  text "DEBUG" at 39.395,2.845 h1.4
  text "20190315 V1.0" at 17.957,2.515 h1.27
  text "CHRG" at 45.517,1.676 h1.4
  text "ANT" at 24.46,0.813 h1.4
  text "PWR" at 57.607,0.254 h1.4
Bottom Overlay:
  circle w0.508: c26.137,4.432 r0.254
  circle w0.508: c20.625,6.109 r0.254
  circle w0.508: c26.137,6.109 r0.254
  circle w0.508: c21.768,9.792 r0.254
  circle w0.508: c19.329,9.792 r0.254
  circle w0.508: c23.546,11.468 r0.254
  circle w0.508: c26.162,11.468 r0.254
  circle w0.508: c26.162,13.348 r0.254
  rectangle: 22.047,4.064 24.994,4.801
  rectangle: 22.047,5.74 24.994,6.477
  rectangle: 16.205,7.671 19.152,8.407
  rectangle: 19.863,7.671 22.809,8.407
  rectangle: 23.647,7.671 26.594,8.407
  rectangle: 23.647,9.423 26.594,10.16
  rectangle: 18.44,12.979 21.387,13.716
  rectangle: 22.073,12.979 25.019,13.716
  lines w0.127: 7.1,21.42 57.892,21.42 ; 7.1,23.96 57.892,23.96 ; 9.64,18.88 9.64,29.04 ; 12.18,18.88 12.18,29.04 ; 14.72,18.88 14.72,29.04 ; 17.26,18.88 17.26,29.04 ; 19.8,18.88 19.8,29.04 ; 22.34,18.88 22.34,29.04 ; 24.88,18.88 24.88,29.04 ; 27.42,18.88 27.42,29.04 ; 29.96,18.8 29.96,29.04 ; 32.5,18.88 32.5,29.04 ; 33.782,6.553 49.022,6.553 ; 35.04,18.88 35.04,29.04 ; 36.322,9.093 36.322,4.013 38.862,3 38.862,0.203 ; 37.58,18.88 37.58,29.04 ; 38.862,9.093 38.862,4.013 40.132,3 40.132,0.203 ; 40.12,18.88 40.12,29.04 ; 41.4,0.229 41.4,9.093 ; 42.66,18.88 42.66,29.04 ; 42.672,0.203 42.672,3 43.942,4.013 43.942,4.5 43.942,9.093 ; 43.942,0.203 43.942,3 46.482,4.013 46.482,9.093 ; 45.2,18.88 45.2,29.04 ; 47.74,18.88 47.74,29.04 ; 50.28,18.88 50.28,29.04 ; 52.82,16.383 52.82,13.8 55.36,13.8 ; 52.82,29.04 52.82,16.34 57.894,16.34 ; 55.36,29.04 55.36,13.8 ; 57.892,18.8 7.1,18.8 7.1,29.04 57.9,29.04 ; 57.9,18.618 57.9,29.04 ; 33.782,4.013 37.592,0.203 45.212,0.203 49.022,4.013 ; 33.782,4.013 33.782,4.5 33.782,9.093 49.022,9.093 49.022,4.5 49.022,4.013 ; 33.782,4.013 49.022,4.013 ; 55.36,13.8 57.9,13.8 57.9,29.04
  text "21" at 26.187,21.967 h1.4 r315
  text "19" at 33.879,21.947 h1.4 r315
  text "18" at 36.422,21.947 h1.4 r315
  text "17" at 38.953,21.943 h1.4 r315
  text "14" at 46.581,21.944 h1.4 r315
  text "12" at 51.664,21.946 h1.4 r315
  text "35" at 21.225,21.916 h1.4 r315
  text "20" at 28.86,21.913 h1.4 r315
  text "5V" at 8.636,21.854 h1.4 r315
  text "5V" at 11.179,21.854 h1.4 r315
  text "TX1" at 16.383,21.646 h1.4 r315
  text "RX1" at 18.946,21.621 h1.4 r315
  text "GND" at 14.021,21.548 h1.27 r315
  text "SCL" at 41.935,21.543 h1.4 r315
  text "GND" at 24.206,21.432 h1.4 r315
  text "GND" at 31.801,21.432 h1.4 r315
  text "GND" at 44.552,21.432 h1.4 r315
  text "GND" at 49.632,21.432 h1.4 r315
  text "16" at 44.145,19.366 h1.4 r315
  text "15" at 46.66,19.364 h1.4 r315
  text "13" at 49.124,19.366 h1.4 r315
  text "MI" at 33.884,19.355 h1.4 r315
  text "33" at 51.74,19.337 h1.4 r315
  text "34" at 56.871,19.338 h1.4 r315
  text "25" at 16.154,19.328 h1.4 r315
  text "24" at 21.243,19.326 h1.4 r315
  text "23" at 23.791,19.33 h1.4 r315
  text "22" at 26.391,19.328 h1.4 r315
  text "32" at 54.204,19.329 h1.4 r315
  text "MO" at 31.598,19.126 h1.4 r315
  text "3V3" at 8.865,18.948 h1.52 r315
  text "3V3" at 29.21,18.948 h1.52 r315
  text "CLK" at 36.805,18.948 h1.4 r315
  text "SDA" at 11.532,18.898 h1.4 r315
  text "SDA" at 42.012,18.898 h1.4 r315
  text "SCL" at 14.021,18.872 h1.52 r315
  text "GND" at 19.177,18.85 h1.4 r315
  text "GND" at 39.472,18.847 h1.4 r315
  text "11" at 54.153,16.942 h1.4 r315
  text "GND" at 57.277,16.307 h1.4 r315
  text "BAT" at 57.125,13.919 h1.4 r315
  text "GND" at 54.712,13.843 h1.4 r315
  text "GND" at 48.641,9.855 h1.52
  text "R" at 49.784,9.855 h1.52
  text "T" at 51.13,9.855 h1.52
  text "widora.io" at 62.357,9.5 h3 r270
  text "IO0" at 48.057,6.858 h1.4 r315
  text "RST" at 35.56,6.667 h1.4 r315
  text "KEY" at 38.049,6.658 h1.4 r315
  text "WTX" at 40.742,6.528 h1.3 r315
  text "WEN" at 45.847,6.528 h1.3 r315
  text "WRX" at 43.307,6.502 h1.3 r315
  text "TDI" at 40.386,4.318 h1.4 r315
  text "3V3" at 35.484,4.242 h1.4 r315
  text "TCK" at 38.176,4.115 h1.4 r315
  text "TMS" at 43.205,4.089 h1.4 r315
  text "TDO" at 45.72,4.089 h1.4 r315
  text "GND" at 48.387,4.039 h1.4 r315
  text "Designed by Yuan" at 11.709,0.508 h2.2 r315
Top Solder:
  circle w1.625: c3.5,3.5 r2.18
  circle w1.625: c3.5,26.5 r2.18
  circle w1.625: c61.5,26.5 r2.18
  circle w1.625: c61.5,3.5 r2.18
Bottom Solder:
  circle w1.625: c3.5,3.5 r2.18
  circle w1.625: c3.5,26.5 r2.18
  circle w1.625: c61.5,26.5 r2.18
  circle w1.625: c61.5,3.5 r2.18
